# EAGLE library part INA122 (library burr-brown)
Instrumentation Amplifier Single Supply, MicroPower
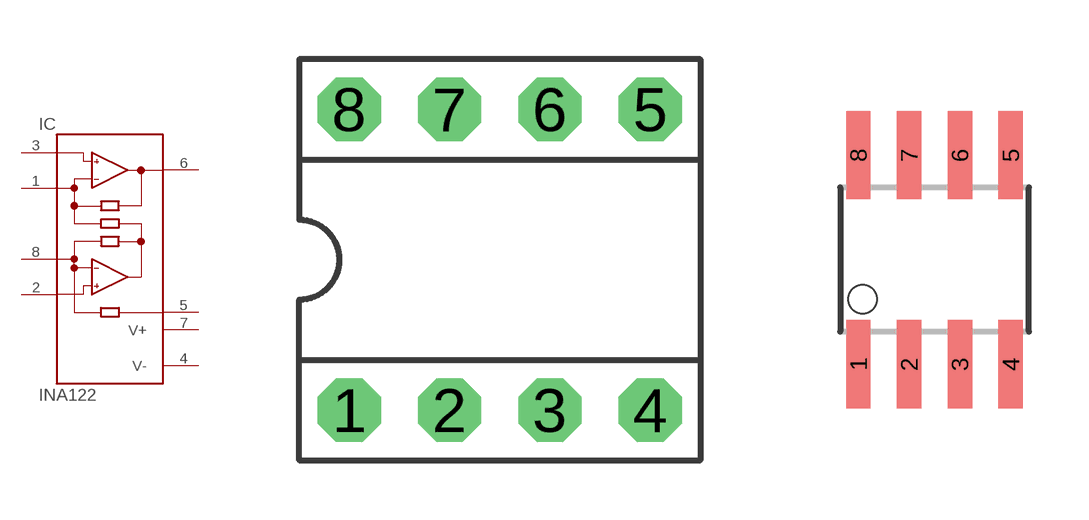
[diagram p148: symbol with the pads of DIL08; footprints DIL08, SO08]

Designator prefix IC

## INA122P (MF: TEXAS INSTRUMENTS; MPN: INA122P; OC_FARNELL: 1459460; OC_NEWARK: 15M0948)  [DIL08]
1  RG  pas
2  -IN  in
3  +IN  in
4  V-  pwr
5  REF  pas
6  OUT  out
7  V+  pwr
8  RG  pas

## INA122U (MPN: INA122U; OC_FARNELL: 1212407; OC_NEWARK: 97K1918)  [SO08]
Pads as for DIL08

## Footprint DIL08 (pad centres in mm)
Dual In Line
drill 0.813 pad 1.6 octagon: 1 -3.81,-3.81; 2 -1.27,-3.81; 3 1.27,-3.81; 4 3.81,-3.81; 5 3.81,3.81; 6 1.27,3.81; 7 -1.27,3.81; 8 -3.81,3.81

## Footprint SO08 (pad centres in mm)
Small Outline Package
smd 0.61 x 2.21: 1 -1.905,-2.616; 2 -0.635,-2.616; 3 0.635,-2.616; 4 1.905,-2.616; 5 1.905,2.616; 6 0.635,2.616; 7 -0.635,2.616; 8 -1.905,2.616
